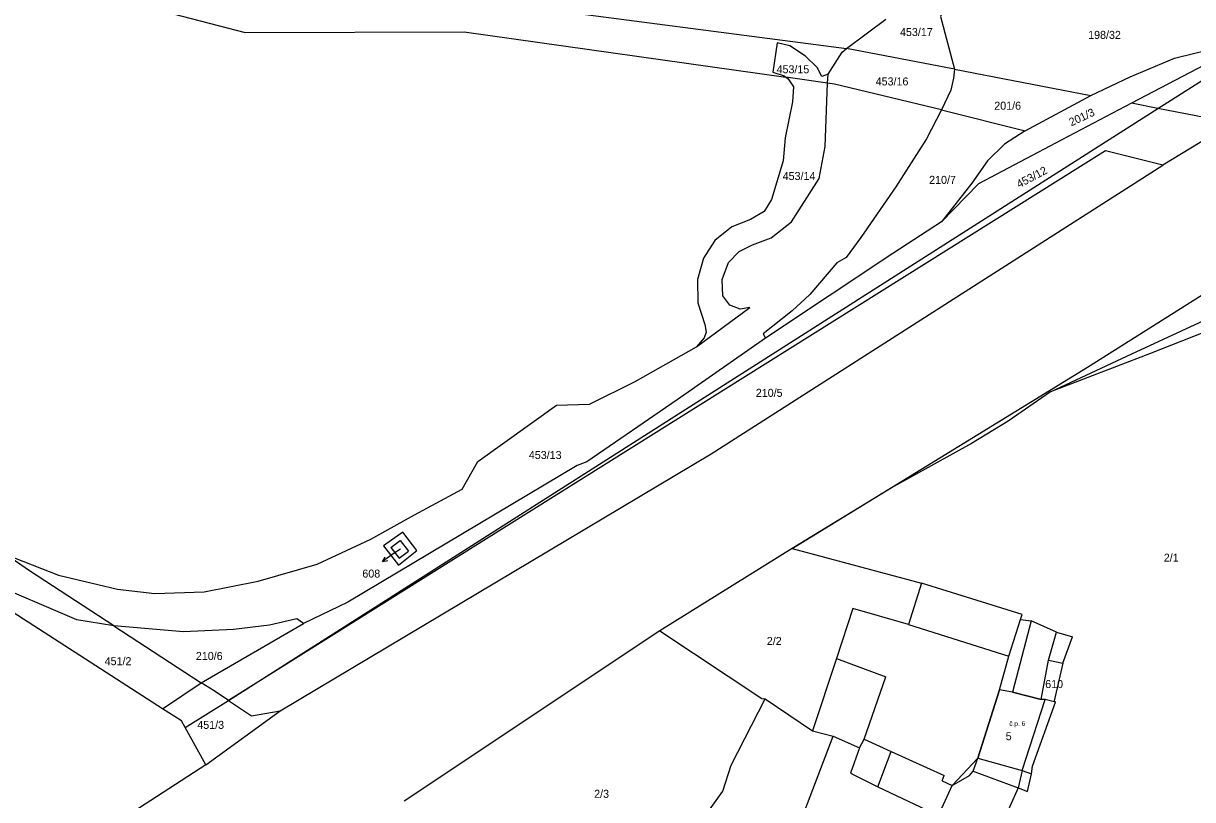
# Model space of a CAD drawing. Extents: x -882150 to -879379, y -1022570 to -1019819.
# Drawn here: x -880738 to -880489.6, y -1021170.2 to -1021005.3 of the extents above; entities that cross this region are included whole.
import ezdxf

# ---------------------------------------------------------------- set-up
doc = ezdxf.new("R2010")
doc.units = 0
for name, color, linetype in [('Definiční body', 7, 'Continuous'), ('Hranice parcel', 7, 'Continuous'), ('Parcelní čísla', 7, 'Continuous'), ('Polygon budovy', 7, 'Continuous'), ('Pop  PČ popisy', 7, 'Continuous'), ('Vnitřní kresba', 7, 'Continuous')]:
    doc.layers.add(name, color=color, linetype=linetype)

msp = doc.modelspace()

# ---------------------------------------------------------------- linework, layer by layer
at = {"layer": 'Hranice parcel'}
for p, q in [((-880563.15, -1021010.65), (-880554.77, -1021004.39)), ((-880476.16, -1021008.4), (-880502.57, -1021022.27)), ((-880567.07, -1021016.1), (-880564.06, -1021011.43)), ((-880564.06, -1021011.43), (-880563.15, -1021010.65)), ((-880540.22, -1021015.05), (-880563.15, -1021010.65)), ((-880567.15, -1021017.98), (-880576.05, -1021016.73)), ((-880567.15, -1021017.98), (-880567.07, -1021016.1)), ((-880540.22, -1021015.05), (-880511.24, -1021020.61)), ((-880525.2, -1021028.1), (-880511.24, -1021020.61)), ((-880542.96, -1021023.66), (-880525.2, -1021028.1)), ((-880502.57, -1021022.27), (-880517.37, -1021030.05)), ((-880481.22, -1021026.44), (-880495.95, -1021035.41)), ((-880495.95, -1021035.41), (-880508.09, -1021032.37)), ((-880553.09, -1021103.67), (-880574.71, -1021116.82)), ((-880574.71, -1021116.82), (-880602.77, -1021134.34)), ((-880574.71, -1021116.82), (-880547.18, -1021124.22)), ((-880708.46, -1021150.88), (-880742.42, -1021129.02)), ((-880718.82, -1021133.31), (-880700.29, -1021145.4)), ((-880700.29, -1021145.4), (-880678.54, -1021132.76)), ((-880523.9, -1021132.2), (-880527.9, -1021147.4)), ((-880602.77, -1021134.34), (-880657.13, -1021170.56)), ((-880708.46, -1021150.88), (-880700.29, -1021145.4)), ((-880580.4, -1021148.8), (-880570.4, -1021155.6)), ((-880699.29, -1021162.79), (-880683.48, -1021151.34)), ((-880702.61, -1021156.8), (-880703.66, -1021154.89)), ((-880570.4, -1021155.6), (-880566, -1021156.7)), ((-880699.29, -1021162.79), (-880702.61, -1021156.8))]:
    msp.add_line(p, q, dxfattribs=at)
for points in [[(-881008.12, -1020866.43), (-880993.59, -1020876.88), (-880968.62, -1020891.12), (-880928.33, -1020911.7), (-880888.23, -1020930.64), (-880844.76, -1020949.33), (-880798.1, -1020971.47), (-880770.61, -1020982.51), (-880725.04, -1020998.33), (-880690.89, -1021007.2), (-880644.38, -1021007.09), (-880576.05, -1021016.73)], [(-880524.39, -1020977.22), (-880525.49, -1020976.89), (-880526.51, -1020977.24), (-880531.17, -1020982.39), (-880534.21, -1020986.35), (-880536.84, -1020990.58), (-880540.01, -1020996.68), (-880543.15, -1021003.81), (-880540.22, -1021015.05)], [(-880574.71, -1021116.82), (-880511.95, -1021078.31), (-880468.39, -1021050.82), (-880418.11, -1021018.15), (-880374.5, -1020983.56)], [(-880675.05, -1021000), (-880644.2, -1021000), (-880634.88, -1021001.29), (-880563.15, -1021010.65)], [(-880567.07, -1021016.1), (-880568.36, -1021016.59), (-880569.38, -1021014.67), (-880571.84, -1021012.24), (-880575.16, -1021010.07), (-880577.86, -1021009.41), (-880578.78, -1021015.64), (-880576.41, -1021016.45), (-880576.05, -1021016.73)], [(-880511.24, -1021020.61), (-880502.88, -1021016.62), (-880493.44, -1021012.65), (-880476.16, -1021008.4)], [(-880576.05, -1021016.73), (-880575.56, -1021017.1), (-880574.41, -1021018.74), (-880574.61, -1021021.93), (-880576.16, -1021029.61), (-880576.58, -1021034.51), (-880579.06, -1021042.68), (-880580.66, -1021045.25), (-880583.56, -1021046.92), (-880587.49, -1021048.48), (-880591.1, -1021051.38), (-880593.56, -1021055.18), (-880594.81, -1021059.71), (-880594.7, -1021064.64), (-880593.22, -1021069.25), (-880592.96, -1021070.86), (-880593.37, -1021072.06), (-880595, -1021073.97)], [(-880540.22, -1021015.05), (-880540.38, -1021016.9), (-880540.98, -1021019.47), (-880542.96, -1021023.66)], [(-880595, -1021073.97), (-880583.67, -1021065.68), (-880585.76, -1021066.02), (-880587.93, -1021065.17), (-880589.39, -1021063.2), (-880589.58, -1021059.72), (-880588.19, -1021056.06), (-880585.98, -1021053.78), (-880583.12, -1021052.35), (-880579.13, -1021050.83), (-880574.81, -1021047.47), (-880568.96, -1021038.27), (-880567.68, -1021031.42), (-880567.15, -1021017.98)], [(-880542.96, -1021023.66), (-880565.66, -1021018.19), (-880567.15, -1021017.98)], [(-880542.96, -1021023.66), (-880546.14, -1021029.85), (-880552.64, -1021040.02), (-880560.07, -1021050.8), (-880563.23, -1021055.06), (-880565.18, -1021056.19), (-880570.94, -1021062.9), (-880574.65, -1021066.33), (-880580.83, -1021071.26), (-880580.32, -1021072.19)], [(-880481.22, -1021026.44), (-880497.01, -1021023.34), (-880502.57, -1021022.27)], [(-880525.2, -1021028.1), (-880529.6, -1021030.95), (-880533.21, -1021034.48), (-880536.49, -1021039.25), (-880542.93, -1021047.42)], [(-880517.37, -1021030.05), (-880535.09, -1021039.36), (-880542.93, -1021047.42)], [(-880508.09, -1021032.37), (-880608.92, -1021095.53), (-880694.49, -1021149.14)], [(-880683.48, -1021151.34), (-880591.88, -1021096.74), (-880495.95, -1021035.41)], [(-880542.93, -1021047.42), (-880553.27, -1021054.15), (-880580.32, -1021072.19)], [(-880519.8, -1021083.58), (-880502.52, -1021075.49), (-880481.4, -1021065.7), (-880468.96, -1021064.18), (-880466.73, -1021064.99), (-880463.43, -1021077.08), (-880462.9, -1021093.7)], [(-880462.9, -1021093.7), (-880465.35, -1021083.05), (-880470.69, -1021071.03), (-880472.67, -1021065.21), (-880498.73, -1021075.48), (-880519.8, -1021083.58)], [(-880741.74, -1021118.14), (-880730.61, -1021122.5), (-880718.07, -1021125.52), (-880710.14, -1021126.42), (-880699.64, -1021126.04), (-880688.12, -1021123.8), (-880675.65, -1021120.2), (-880664.19, -1021114.9), (-880654.95, -1021109.67), (-880644.84, -1021104.25), (-880641.46, -1021098.4), (-880624.77, -1021086.37), (-880617.73, -1021086.2), (-880608.05, -1021081.34), (-880595, -1021073.97)], [(-880580.32, -1021072.19), (-880599.12, -1021085.26), (-880618.33, -1021098.46), (-880620.39, -1021099.24), (-880669.08, -1021128.26), (-880678.54, -1021132.76)], [(-880519.8, -1021083.58), (-880528.82, -1021089.83), (-880536.61, -1021094.54), (-880553.09, -1021103.67)], [(-880657.39, -1021113.35), (-880661.49, -1021116.29), (-880658.32, -1021120.41), (-880654.46, -1021117.27), (-880657.39, -1021113.35)], [(-880718.82, -1021133.31), (-880736.75, -1021121.61), (-880741.74, -1021118.14)], [(-880718.82, -1021133.31), (-880726.69, -1021131.99), (-880745.98, -1021123.8), (-880753.72, -1021119.65)], [(-880547.18, -1021124.22), (-880549.99, -1021133.02), (-880561.8, -1021129.6), (-880565.29, -1021140.25), (-880570.4, -1021155.6)], [(-880527.9, -1021147.4), (-880530.63, -1021146.85), (-880528.67, -1021139.71), (-880526.16, -1021131.96), (-880525.8, -1021130.87), (-880547.18, -1021124.22)], [(-880678.54, -1021132.76), (-880679.96, -1021131.78), (-880685.78, -1021133.17), (-880693.38, -1021134.06), (-880704, -1021134.55), (-880718.82, -1021133.31)], [(-880520.2, -1021140.6), (-880518.5, -1021134.6), (-880523.9, -1021132.2)], [(-880602.77, -1021134.34), (-880581.15, -1021148.69), (-880580.4, -1021148.8)], [(-880518.71, -1021149.49), (-880520.9, -1021148.9), (-880521.8, -1021148.9), (-880520.2, -1021140.6)], [(-880520.2, -1021140.6), (-880517.2, -1021141.2), (-880519, -1021149.2), (-880518.71, -1021149.49)], [(-880694.49, -1021149.14), (-880697.53, -1021147.12), (-880700.29, -1021145.4)], [(-880602.45, -1021186.68), (-880589.43, -1021168.38), (-880587.64, -1021162.87), (-880580.4, -1021148.8)], [(-880703.66, -1021154.89), (-880704.46, -1021153.45), (-880708.46, -1021150.88)], [(-880694.49, -1021149.14), (-880689.57, -1021152.4), (-880683.48, -1021151.34)], [(-880525.8, -1021164), (-880523.8, -1021164.7), (-880523.6, -1021163.1), (-880518.71, -1021149.49)], [(-880572.81, -1021193.74), (-880578.34, -1021189.21), (-880566, -1021156.7)], [(-880566, -1021156.7), (-880560.4, -1021159.2), (-880562.3, -1021164.6), (-880556.46, -1021167.45), (-880543.6, -1021173.6)], [(-880699.29, -1021162.79), (-880808.35, -1021233.5), (-880873.35, -1021274.78), (-880941.52, -1021318.31), (-881007.7, -1021360.64), (-881104.49, -1021422.63)], [(-880543.6, -1021173.6), (-880540.67, -1021167.18), (-880535.26, -1021161.4), (-880525.8, -1021164)], [(-880525.8, -1021164), (-880526.67, -1021167.7), (-880528.44, -1021171.66), (-880539.35, -1021197.25)]]:
    msp.add_lwpolyline(points, dxfattribs=at)
at = {"layer": 'Polygon budovy'}
msp.add_lwpolyline([(-880525.8, -1021164), (-880520.9, -1021148.9), (-880521.8, -1021148.9), (-880527.9, -1021147.4), (-880530.63, -1021146.85), (-880535.26, -1021161.4)], close=True, dxfattribs=at)
at = {"layer": 'Pop  PČ popisy'}
for p, q in [((-880659.25, -1021117.87), (-880661.708, -1021119.591)), ((-880661.708, -1021119.591), (-880661.175, -1021118.607)), ((-880657.94, -1021116.97), (-880659.25, -1021117.87)), ((-880661.708, -1021119.591), (-880660.601, -1021119.427))]:
    msp.add_line(p, q, dxfattribs=at)
at = {"layer": 'Vnitřní kresba'}
for p, q in [((-880497.01, -1021023.34), (-880353.65, -1020933.14)), ((-880694.49, -1021149.14), (-880497.01, -1021023.34)), ((-880659.93, -1021116.63), (-880657.99, -1021115.14)), ((-880659.93, -1021116.63), (-880658.16, -1021118.9)), ((-880657.99, -1021115.14), (-880656.22, -1021117.4)), ((-880658.16, -1021118.9), (-880656.22, -1021117.4)), ((-880549.99, -1021133.02), (-880528.67, -1021139.71)), ((-880526.16, -1021131.96), (-880523.9, -1021132.2)), ((-880518.5, -1021134.6), (-880515.14, -1021135.63)), ((-880517.2, -1021141.2), (-880515.14, -1021135.63)), ((-880565.29, -1021140.25), (-880554.75, -1021144.13)), ((-880559.39, -1021157.35), (-880554.75, -1021144.13)), ((-880535.26, -1021161.4), (-880530.63, -1021146.85)), ((-880527.9, -1021147.4), (-880521.8, -1021148.9)), ((-880525.8, -1021164), (-880520.9, -1021148.9)), ((-880703.66, -1021154.89), (-880694.49, -1021149.14)), ((-880560.4, -1021159.2), (-880559.39, -1021157.35)), ((-880559.39, -1021157.35), (-880553.65, -1021159.95)), ((-880554.43, -1021162.02), (-880553.65, -1021159.95)), ((-880553.65, -1021159.95), (-880542.41, -1021165.08)), ((-880556.46, -1021167.45), (-880554.43, -1021162.02)), ((-880536.19, -1021164.16), (-880535.26, -1021161.4)), ((-880542.8, -1021166.18), (-880542.41, -1021165.08)), ((-880542.8, -1021166.18), (-880540.67, -1021167.18)), ((-880540.67, -1021167.18), (-880536.97, -1021165.05)), ((-880536.97, -1021165.05), (-880536.19, -1021164.16)), ((-880536.19, -1021164.16), (-880526.67, -1021167.7)), ((-880524.68, -1021168.44), (-880523.8, -1021164.7)), ((-880526.67, -1021167.7), (-880524.68, -1021168.44))]:
    msp.add_line(p, q, dxfattribs=at)

# ---------------------------------------------------------------- texts
at = {"layer": 'Definiční body'}
msp.add_text('č.p. 6', height=1, dxfattribs=at).set_placement((-880528.54, -1021154.54))
at = {"layer": 'Parcelní čísla'}
for s, p in [('453/17', (-880551.77, -1021007.98)), ('198/32', (-880511.79, -1021008.58)), ('453/15', (-880578, -1021015.89)), ('453/16', (-880556.94, -1021018.47)), ('201/6', (-880531.74, -1021023.63)), ('453/14', (-880576.7, -1021038.56)), ('210/7', (-880545.58, -1021039.38)), ('210/5', (-880582.41, -1021084.63)), ('453/13', (-880630.64, -1021097.83)), ('2/1', (-880495.72, -1021119.65)), ('608', (-880666.014, -1021123.028)), ('2/2', (-880580.07, -1021137.34)), ('210/6', (-880701.39, -1021140.53)), ('451/2', (-880720.77, -1021141.64)), ('610', (-880520.92, -1021146.5)), ('451/3', (-880701.09, -1021155.17)), ('5', (-880529.31, -1021157.58)), ('2/3', (-880616.76, -1021169.81))]:
    msp.add_text(s, height=1.7, dxfattribs=at).set_placement(p)
for s, rotation, p in [('201/3', 25, (-880515.377, -1021027.174)), ('453/12', 28, (-880526.44, -1021040.32))]:
    msp.add_text(s, height=1.7, rotation=rotation, dxfattribs=at).set_placement(p)

doc.saveas('drawing.dxf')
